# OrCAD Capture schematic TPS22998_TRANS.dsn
size A; title: TPS22998 5.5-V, 10-A, 4-mO On-Resistance load switch; rev: 1.0; note: Datasheet: SLVSG05  EVM User's Guide: SLVUCB6
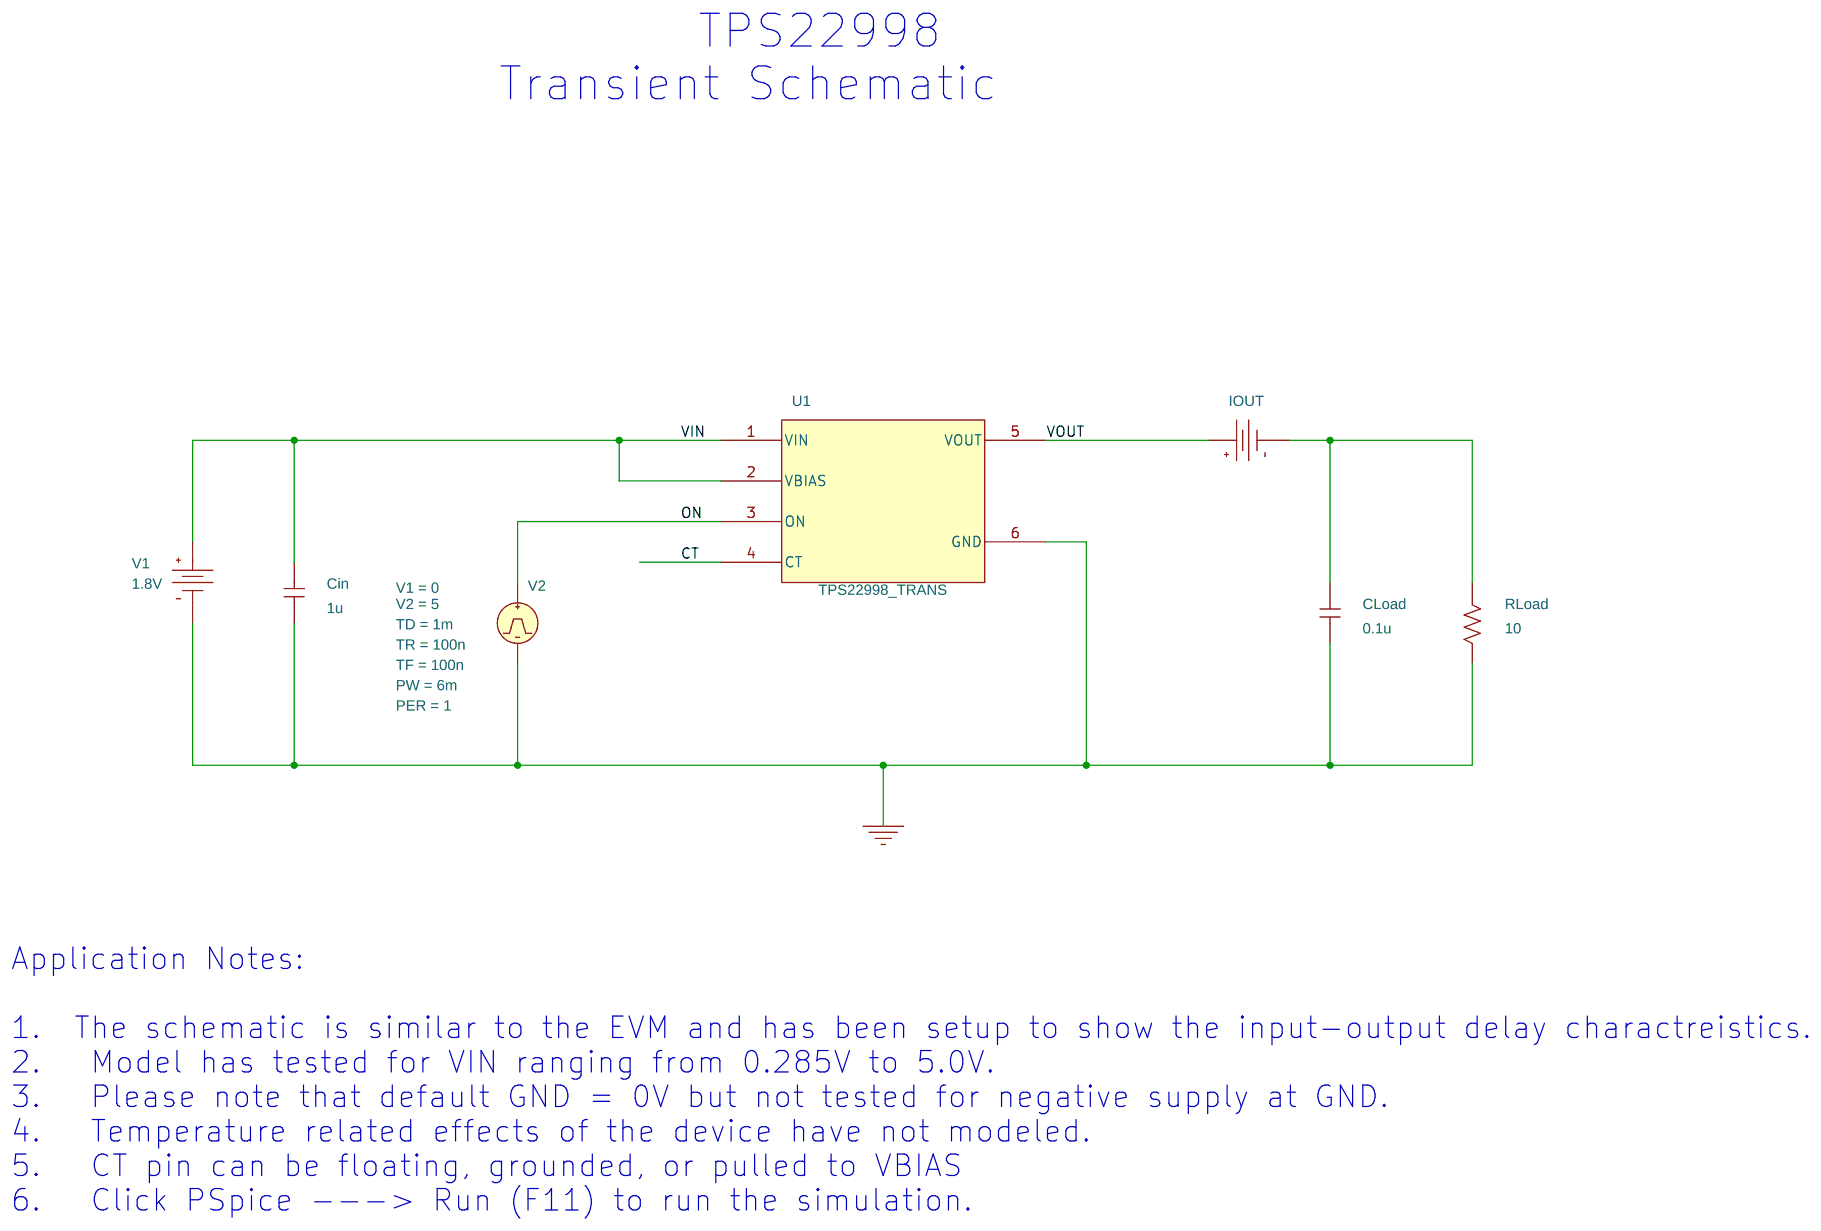
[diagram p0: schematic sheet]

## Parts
Cin  1u  [RAD/CK05]
CLoad  0.1u  [RAD/CK05]
IOUT  VDC
RLoad  10  [AX/RC05]
U1  TPS22998_TRANS
V1  VDC
V2  VPULSE

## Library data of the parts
Cin CLoad = C: IC: 0
IOUT = VDC
RLoad = R
U1 = TPS22998_TRANS
V1 = VDC: DC: 1.8V
V2 = VPULSE: PER: 1; PW: 6m; TD: 1m; TF: 100n; TR: 100n; V1: 0; V2: 5

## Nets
VIN: Cin.2 U1.1(VIN) U1.2(VBIAS) V1.0(+)
0: Cin.1 CLoad.1 RLoad.2 U1.6(GND) V1.1(-) V2.2(-)
CT: U1.4(CT)
ON: U1.3(ON) V2.1(+)
VOUT: IOUT.0(+) U1.5(VOUT)
N16774938: CLoad.2 IOUT.1(-) RLoad.1

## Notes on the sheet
- TPS22998
  Transient Schematic
- Application Notes:
  1.  The schematic is similar to the EVM and has been setup to show the input-output delay charactreistics.
  2.   Model has tested for VIN ranging from 0.285V to 5.0V.
  3.   Please note that default GND = 0V but not tested for negative supply at GND.
  4.   Temperature related effects of the device have not modeled.
  5.   CT pin can be floating, grounded, or pulled to VBIAS
  6.   Click PSpice ---> Run (F11) to run the simulation.
